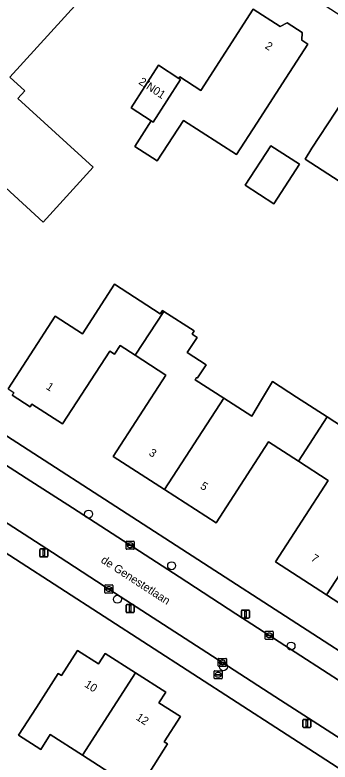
# Model space of a CAD drawing. Extents: x 161139 to 161601, y 381708 to 382245.
# Drawn here: x 161355.3 to 161394.2, y 382017.4 to 382109.7 of the extents above; entities that cross this region are included whole.
import ezdxf

# ---------------------------------------------------------------- set-up
doc = ezdxf.new("R2010")
doc.units = 0
for name, color, linetype in [('IMGEO_Boom', 7, 'Continuous'), ('IMGEO_Brandkraan', 7, 'Continuous'), ('IMGEO_Erf', 7, 'Continuous'), ('IMGEO_Kolk', 7, 'Continuous'), ('IMGEO_Lichtmast', 7, 'Continuous'), ('IMGEO_Openbare_ruimte_label', 7, 'Continuous'), ('IMGEO_Pand', 7, 'Continuous'), ('IMGEO_Pand_nummerreeks', 7, 'Continuous'), ('IMGEO_Rijbaan_lokaal_open', 7, 'Continuous'), ('IMGEO_Voetpad_open', 7, 'Continuous')]:
    doc.layers.add(name, color=color, linetype=linetype)

msp = doc.modelspace()

# ---------------------------------------------------------------- linework, layer by layer
at = {"layer": 'IMGEO_Boom'}
for centre in [(161364.4, 382048.05), (161374.648, 382041.67), (161367.953, 382037.533), (161389.384, 382031.752), (161381.04, 382029.2)]:
    msp.add_circle(centre, 0.489, dxfattribs=at)
at = {"layer": 'IMGEO_Brandkraan'}
for p, q in [((161379.895, 382027.782), (161379.895, 382028.634)), ((161379.97, 382028.708), (161380.822, 382028.708)), ((161380.383, 382028.488), (161380.408, 382028.488)), ((161380.896, 382028.634), (161380.896, 382027.782)), ((161380.822, 382027.708), (161379.97, 382027.708)), ((161380.154, 382028.202), (161380.154, 382028.214)), ((161380.592, 382028.165), (161380.194, 382028.165)), ((161380.197, 382028.251), (161380.595, 382028.251)), ((161380.406, 382027.928), (161380.381, 382027.928)), ((161380.638, 382028.214), (161380.638, 382028.202))]:
    msp.add_line(p, q, dxfattribs=at)
for points in [[(161379.895, 382027.782), (161379.895, 382028.634)], [(161379.97, 382028.708), (161380.822, 382028.708)], [(161380.896, 382028.634), (161380.896, 382027.782)], [(161380.822, 382027.708), (161379.97, 382027.708)]]:
    msp.add_lwpolyline(points, dxfattribs=at)
for centre, radius, start, end in [((161379.972, 382028.632), 0.0765, 91.55205, 178.44795), ((161379.972, 382028.632), 0.0765, 91.55205, 178.44795), ((161380.82, 382028.632), 0.0765, 1.55205, 88.44795), ((161380.82, 382028.632), 0.0765, 1.55205, 88.44795), ((161379.972, 382027.784), 0.0765, 181.55205, 268.44795), ((161379.972, 382027.784), 0.0765, 181.55205, 268.44795), ((161380.194, 382028.211), 0.0403, 85.87752, 175.75265), ((161380.191, 382028.201), 0.0366, 178.93798, 274.71019), ((161380.595, 382028.208), 0.043, 264.86636, 352.45326), ((161380.599, 382028.213), 0.0386, 1.73085, 96.63898), ((161380.82, 382027.784), 0.0765, 271.55205, 358.44795), ((161380.82, 382027.784), 0.0765, 271.55205, 358.44795)]:
    msp.add_arc(centre, radius, start, end, dxfattribs=at)
for centre, major_axis, ratio, start_param, end_param in [((161380.382, 382028.208), (-0.387, 0.002), 0.722429, 4.712389, 7.853982), ((161380.407, 382028.208), (-0.39, 0.002), 0.717154, 1.570796, 4.712389)]:
    msp.add_ellipse(centre, major_axis=major_axis, ratio=ratio, start_param=start_param, end_param=end_param, dxfattribs=at)
at = {"layer": 'IMGEO_Erf'}
for points in [[(161320.525, 382089.631), (161313.623, 382083.997), (161443.483, 382000), (161462.38, 381987.777), (161470.3, 382000), (161498.24, 382043.117), (161359.011, 382133.266)], [(161346.685, 382109.457), (161347.252, 382108.941), (161354.956, 382117.404), (161355.81, 382116.625), (161358.18, 382119.228), (161364.817, 382113.186), (161354.661, 382102.03), (161356.521, 382100.336), (161355.647, 382099.376), (161364.97, 382090.887), (161358.81, 382084.121)], [(161358.81, 382084.121), (161349.515, 382092.582), (161348.62, 382091.598), (161346.729, 382093.319), (161336.5, 382082.084), (161329.934, 382088.061), (161332.405, 382090.775), (161331.456, 382091.639), (161339.157, 382100.098), (161338.619, 382100.588)], [(161354.467, 382063.546), (161357.185, 382067.744), (161360.263, 382072.498), (161363.625, 382070.32), (161367.586, 382076.436), (161373.234, 382072.779), (161373.506, 382073.199), (161373.678, 382073.088), (161377.409, 382070.671), (161377.162, 382070.29), (161377.8, 382069.877), (161376.584, 382067.999), (161378.89, 382066.506), (161377.828, 382064.866), (161377.683, 382064.874), (161377.54, 382064.653), (161381.083, 382062.359), (161384.528, 382060.129), (161385.742, 382062.161), (161387.092, 382064.421), (161390.075, 382062.489), (161393.835, 382060.054), (161397.496, 382057.684)], [(161421.048, 382000), (161306.066, 382074.349)], [(161400.087, 382033.974), (161393.772, 382038.063), (161387.46, 382042.15), (161393.97, 382052.203), (161390.289, 382054.594), (161386.608, 382056.985), (161380.125, 382046.974), (161373.783, 382051.081), (161367.441, 382055.187), (161373.936, 382065.217), (161370.156, 382067.673), (161368.301, 382068.878), (161367.614, 382067.814), (161367.026, 382068.194), (161361.193, 382059.186), (161357.399, 382061.642), (161357.171, 382061.289), (161354.949, 382062.728)]]:
    msp.add_lwpolyline(points, dxfattribs=at)
for points in [[(161376.11, 382096.68), (161372.874, 382091.675), (161370.095, 382093.472), (161372.141, 382096.619), (161369.633, 382098.24), (161373.035, 382103.503), (161375.556, 382101.873), (161375.671, 382102.05), (161378.237, 382100.391), (161384.729, 382110.433), (161388.052, 382108.285), (161388.906, 382108.722), (161390.752, 382107.529), (161390.705, 382106.586), (161391.463, 382106.096), (161388.749, 382101.898), (161385.152, 382096.335), (161382.643, 382092.455)], [(161403.739, 382083.736), (161397.438, 382087.809), (161391.146, 382091.877), (161391.97, 382093.238), (161394.864, 382097.714), (161397.578, 382101.913), (161400.051, 382100.314), (161400.18, 382100.512), (161401.027, 382099.965), (161401.953, 382100.163), (161403.047, 382099.456), (161403.251, 382098.506), (161404.008, 382098.017), (161404.764, 382097.529), (161405.713, 382097.732), (161406.876, 382096.98), (161407.084, 382096.013), (161407.959, 382095.447), (161407.856, 382095.287), (161410.219, 382093.759), (161407.505, 382089.561)], [(161387.254, 382086.383), (161383.725, 382088.664), (161386.887, 382093.556), (161390.416, 382091.275)], [(161359.669, 382020.808), (161358.499, 382018.98), (161355.762, 382020.732), (161357.956, 382024.159), (161360.651, 382028.37), (161361.044, 382028.118), (161363.016, 382031.198), (161365.6, 382029.544), (161366.437, 382030.853), (161370.18, 382028.457), (161373.925, 382026.06), (161373.085, 382024.748), (161375.732, 382023.053), (161373.728, 382019.922), (161374.141, 382019.658), (161371.446, 382015.447), (161369.264, 382012.038), (161366.393, 382013.876), (161367.587, 382015.74), (161363.651, 382018.259)]]:
    msp.add_lwpolyline(points, close=True, dxfattribs=at)
at = {"layer": 'IMGEO_Kolk'}
for p, q in [((161369.03, 382043.778), (161369.03, 382044.63)), ((161369.105, 382044.704), (161369.957, 382044.704)), ((161369.289, 382044.198), (161369.289, 382044.21)), ((161369.727, 382044.161), (161369.329, 382044.161)), ((161369.332, 382044.247), (161369.73, 382044.247)), ((161369.518, 382044.484), (161369.543, 382044.484)), ((161369.773, 382044.21), (161369.773, 382044.198)), ((161370.031, 382044.63), (161370.031, 382043.778)), ((161369.957, 382043.704), (161369.105, 382043.704)), ((161369.541, 382043.924), (161369.516, 382043.924)), ((161366.399, 382038.377), (161366.399, 382039.229)), ((161366.474, 382039.303), (161367.326, 382039.303)), ((161366.658, 382038.797), (161366.658, 382038.809)), ((161367.096, 382038.76), (161366.698, 382038.76)), ((161366.701, 382038.846), (161367.099, 382038.846)), ((161366.91, 382038.523), (161366.885, 382038.523)), ((161366.887, 382039.083), (161366.912, 382039.083)), ((161367.142, 382038.809), (161367.142, 382038.797)), ((161367.4, 382039.229), (161367.4, 382038.377)), ((161367.326, 382038.303), (161366.474, 382038.303)), ((161386.19, 382032.649), (161386.19, 382033.501)), ((161386.265, 382033.575), (161387.117, 382033.575)), ((161386.449, 382033.069), (161386.449, 382033.081)), ((161386.887, 382033.032), (161386.489, 382033.032)), ((161386.492, 382033.118), (161386.89, 382033.118)), ((161386.678, 382033.355), (161386.703, 382033.355)), ((161386.933, 382033.081), (161386.933, 382033.069)), ((161387.191, 382033.501), (161387.191, 382032.649)), ((161387.117, 382032.575), (161386.265, 382032.575)), ((161386.701, 382032.795), (161386.676, 382032.795)), ((161380.41, 382029.306), (161380.41, 382030.158)), ((161380.485, 382030.232), (161381.337, 382030.232)), ((161381.411, 382030.158), (161381.411, 382029.306)), ((161381.337, 382029.232), (161380.485, 382029.232)), ((161380.669, 382029.726), (161380.669, 382029.738)), ((161381.107, 382029.689), (161380.709, 382029.689)), ((161380.712, 382029.775), (161381.11, 382029.775)), ((161380.921, 382029.452), (161380.896, 382029.452)), ((161380.898, 382030.012), (161380.923, 382030.012)), ((161381.153, 382029.738), (161381.153, 382029.726))]:
    msp.add_line(p, q, dxfattribs=at)
for points in [[(161369.03, 382043.778), (161369.03, 382044.63)], [(161369.105, 382044.704), (161369.957, 382044.704)], [(161370.031, 382044.63), (161370.031, 382043.778)], [(161369.957, 382043.704), (161369.105, 382043.704)], [(161366.399, 382038.377), (161366.399, 382039.229)], [(161366.474, 382039.303), (161367.326, 382039.303)], [(161367.4, 382039.229), (161367.4, 382038.377)], [(161367.326, 382038.303), (161366.474, 382038.303)], [(161386.19, 382032.649), (161386.19, 382033.501)], [(161386.265, 382033.575), (161387.117, 382033.575)], [(161387.191, 382033.501), (161387.191, 382032.649)], [(161387.117, 382032.575), (161386.265, 382032.575)], [(161380.41, 382029.306), (161380.41, 382030.158)], [(161380.485, 382030.232), (161381.337, 382030.232)], [(161381.411, 382030.158), (161381.411, 382029.306)], [(161381.337, 382029.232), (161380.485, 382029.232)]]:
    msp.add_lwpolyline(points, dxfattribs=at)
for centre, radius, start, end in [((161369.107, 382044.628), 0.0765, 91.55205, 178.44795), ((161369.107, 382044.628), 0.0765, 91.55205, 178.44795), ((161369.329, 382044.207), 0.0403, 85.87752, 175.75265), ((161369.326, 382044.197), 0.0366, 178.93798, 274.71019), ((161369.73, 382044.204), 0.043, 264.86636, 352.45326), ((161369.734, 382044.209), 0.0386, 1.73085, 96.63898), ((161369.955, 382044.628), 0.0765, 1.55205, 88.44795), ((161369.955, 382044.628), 0.0765, 1.55205, 88.44795), ((161369.107, 382043.78), 0.0765, 181.55205, 268.44795), ((161369.107, 382043.78), 0.0765, 181.55205, 268.44795), ((161369.955, 382043.78), 0.0765, 271.55205, 358.44795), ((161369.955, 382043.78), 0.0765, 271.55205, 358.44795), ((161366.476, 382039.227), 0.0765, 91.55205, 178.44795), ((161366.476, 382039.227), 0.0765, 91.55205, 178.44795), ((161366.698, 382038.806), 0.0403, 85.87752, 175.75265), ((161366.695, 382038.796), 0.0366, 178.93798, 274.71019), ((161367.099, 382038.803), 0.043, 264.86636, 352.45326), ((161367.103, 382038.808), 0.0386, 1.73085, 96.63898), ((161367.324, 382039.227), 0.0765, 1.55205, 88.44795), ((161367.324, 382039.227), 0.0765, 1.55205, 88.44795), ((161366.476, 382038.379), 0.0765, 181.55205, 268.44795), ((161366.476, 382038.379), 0.0765, 181.55205, 268.44795), ((161367.324, 382038.379), 0.0765, 271.55205, 358.44795), ((161367.324, 382038.379), 0.0765, 271.55205, 358.44795), ((161386.267, 382033.499), 0.0765, 91.55205, 178.44795), ((161386.267, 382033.499), 0.0765, 91.55205, 178.44795), ((161386.489, 382033.078), 0.0403, 85.87752, 175.75265), ((161386.486, 382033.068), 0.0366, 178.93798, 274.71019), ((161386.89, 382033.075), 0.043, 264.86636, 352.45326), ((161386.894, 382033.08), 0.0386, 1.73085, 96.63898), ((161387.115, 382033.499), 0.0765, 1.55205, 88.44795), ((161387.115, 382033.499), 0.0765, 1.55205, 88.44795), ((161386.267, 382032.651), 0.0765, 181.55205, 268.44795), ((161386.267, 382032.651), 0.0765, 181.55205, 268.44795), ((161387.115, 382032.651), 0.0765, 271.55205, 358.44795), ((161387.115, 382032.651), 0.0765, 271.55205, 358.44795), ((161380.487, 382030.156), 0.0765, 91.55205, 178.44795), ((161380.487, 382030.156), 0.0765, 91.55205, 178.44795), ((161381.335, 382030.156), 0.0765, 1.55205, 88.44795), ((161381.335, 382030.156), 0.0765, 1.55205, 88.44795), ((161380.487, 382029.308), 0.0765, 181.55205, 268.44795), ((161380.487, 382029.308), 0.0765, 181.55205, 268.44795), ((161380.709, 382029.735), 0.0403, 85.87752, 175.75265), ((161380.706, 382029.725), 0.0366, 178.93798, 274.71019), ((161381.11, 382029.732), 0.043, 264.86636, 352.45326), ((161381.114, 382029.737), 0.0386, 1.73085, 96.63898), ((161381.335, 382029.308), 0.0765, 271.55205, 358.44795), ((161381.335, 382029.308), 0.0765, 271.55205, 358.44795)]:
    msp.add_arc(centre, radius, start, end, dxfattribs=at)
for centre, major_axis, ratio, start_param, end_param in [((161369.517, 382044.204), (-0.387, 0.002), 0.722429, 4.712389, 7.853982), ((161369.542, 382044.204), (-0.39, 0.002), 0.717154, 1.570796, 4.712389), ((161366.886, 382038.803), (-0.387, 0.002), 0.722429, 4.712389, 7.853982), ((161366.911, 382038.803), (-0.39, 0.002), 0.717154, 1.570796, 4.712389), ((161386.677, 382033.075), (-0.387, 0.002), 0.722429, 4.712389, 7.853982), ((161386.702, 382033.075), (-0.39, 0.002), 0.717154, 1.570796, 4.712389), ((161380.897, 382029.732), (-0.387, 0.002), 0.722429, 4.712389, 7.853982), ((161380.922, 382029.732), (-0.39, 0.002), 0.717154, 1.570796, 4.712389)]:
    msp.add_ellipse(centre, major_axis=major_axis, ratio=ratio, start_param=start_param, end_param=end_param, dxfattribs=at)
at = {"layer": 'IMGEO_Lichtmast'}
for p, q in [((161358.366, 382042.857), (161358.366, 382043.657)), ((161358.366, 382043.657), (161358.366, 382042.857)), ((161358.466, 382043.757), (161359.256, 382043.757)), ((161359.256, 382043.757), (161358.466, 382043.757)), ((161359.356, 382043.657), (161359.356, 382042.857)), ((161359.356, 382042.857), (161359.356, 382043.657)), ((161359.256, 382042.757), (161358.466, 382042.757)), ((161358.466, 382042.757), (161359.256, 382042.757)), ((161369.024, 382035.985), (161369.024, 382036.785)), ((161369.024, 382036.785), (161369.024, 382035.985)), ((161369.124, 382036.885), (161369.914, 382036.885)), ((161369.914, 382036.885), (161369.124, 382036.885)), ((161370.014, 382036.785), (161370.014, 382035.985)), ((161370.014, 382035.985), (161370.014, 382036.785)), ((161369.914, 382035.885), (161369.124, 382035.885)), ((161369.124, 382035.885), (161369.914, 382035.885)), ((161383.26, 382035.3), (161383.26, 382036.1)), ((161383.26, 382036.1), (161383.26, 382035.3)), ((161383.36, 382036.2), (161384.15, 382036.2)), ((161384.15, 382036.2), (161383.36, 382036.2)), ((161384.25, 382036.1), (161384.25, 382035.3)), ((161384.25, 382035.3), (161384.25, 382036.1)), ((161384.15, 382035.2), (161383.36, 382035.2)), ((161383.36, 382035.2), (161384.15, 382035.2)), ((161390.836, 382021.791), (161390.836, 382022.591)), ((161390.836, 382022.591), (161390.836, 382021.791)), ((161390.936, 382022.691), (161391.726, 382022.691)), ((161391.726, 382022.691), (161390.936, 382022.691)), ((161391.826, 382022.591), (161391.826, 382021.791)), ((161391.826, 382021.791), (161391.826, 382022.591)), ((161391.726, 382021.691), (161390.936, 382021.691)), ((161390.936, 382021.691), (161391.726, 382021.691))]:
    msp.add_line(p, q, dxfattribs=at)
for points in [[(161358.786, 382043.632), (161358.936, 382043.632), (161358.936, 382042.882), (161358.786, 382042.882), (161358.786, 382043.632)], [(161369.444, 382036.76), (161369.594, 382036.76), (161369.594, 382036.01), (161369.444, 382036.01), (161369.444, 382036.76)], [(161383.68, 382036.075), (161383.83, 382036.075), (161383.83, 382035.325), (161383.68, 382035.325), (161383.68, 382036.075)], [(161391.256, 382022.566), (161391.406, 382022.566), (161391.406, 382021.816), (161391.256, 382021.816), (161391.256, 382022.566)]]:
    msp.add_lwpolyline(points, dxfattribs=at)
for centre, start, end in [((161358.466, 382043.657), 90, 180), ((161358.466, 382043.657), 90, 180), ((161359.256, 382043.657), 0, 90), ((161359.256, 382043.657), 360, 90), ((161358.466, 382042.857), 180, 270), ((161358.466, 382042.857), 180, 270), ((161359.256, 382042.857), 270, 0), ((161359.256, 382042.857), 270, 0), ((161369.124, 382036.785), 90, 180), ((161369.124, 382036.785), 90, 180), ((161369.914, 382036.785), 0, 90), ((161369.914, 382036.785), 360, 90), ((161369.124, 382035.985), 180, 270), ((161369.124, 382035.985), 180, 270), ((161369.914, 382035.985), 270, 0), ((161369.914, 382035.985), 270, 0), ((161383.36, 382036.1), 90, 180), ((161383.36, 382036.1), 90, 180), ((161384.15, 382036.1), 0, 90), ((161384.15, 382036.1), 360, 90), ((161383.36, 382035.3), 180, 270), ((161383.36, 382035.3), 180, 270), ((161384.15, 382035.3), 270, 0), ((161384.15, 382035.3), 270, 0), ((161390.936, 382022.591), 90, 180), ((161390.936, 382022.591), 90, 180), ((161391.726, 382022.591), 0, 90), ((161391.726, 382022.591), 360, 90), ((161390.936, 382021.791), 180, 270), ((161390.936, 382021.791), 180, 270), ((161391.726, 382021.791), 270, 0), ((161391.726, 382021.791), 270, 0)]:
    msp.add_arc(centre, 0.1, start, end, dxfattribs=at)
at = {"layer": 'IMGEO_Pand'}
msp.add_lwpolyline([(161338.619, 382100.588), (161339.157, 382100.098), (161331.456, 382091.639), (161332.405, 382090.775), (161329.934, 382088.061), (161336.5, 382082.084), (161346.729, 382093.319), (161348.62, 382091.598), (161349.515, 382092.582), (161358.81, 382084.121), (161364.97, 382090.887), (161355.647, 382099.376), (161356.521, 382100.336), (161354.661, 382102.03), (161364.817, 382113.186), (161358.18, 382119.228), (161355.81, 382116.625), (161354.956, 382117.404), (161347.252, 382108.941), (161346.685, 382109.457)], dxfattribs=at)
for points in [[(161388.749, 382101.898), (161391.463, 382106.096), (161390.705, 382106.586), (161390.752, 382107.529), (161388.906, 382108.722), (161388.052, 382108.285), (161384.729, 382110.433), (161378.237, 382100.391), (161375.671, 382102.05), (161375.556, 382101.873), (161375.755, 382101.744), (161372.353, 382096.482), (161372.141, 382096.619), (161370.095, 382093.472), (161372.874, 382091.675), (161376.11, 382096.68), (161382.643, 382092.455), (161385.152, 382096.335)], [(161375.556, 382101.873), (161373.035, 382103.503), (161369.633, 382098.24), (161372.141, 382096.619), (161372.353, 382096.482), (161375.755, 382101.744)], [(161397.438, 382087.809), (161404.008, 382098.017), (161403.251, 382098.506), (161403.047, 382099.456), (161401.953, 382100.163), (161401.027, 382099.965), (161400.18, 382100.512), (161400.051, 382100.314), (161397.578, 382101.913), (161394.864, 382097.714), (161391.97, 382093.238), (161391.146, 382091.877)], [(161387.254, 382086.383), (161390.416, 382091.275), (161386.887, 382093.556), (161383.725, 382088.664)], [(161373.678, 382073.088), (161373.506, 382073.199), (161373.234, 382072.779), (161367.586, 382076.436), (161363.625, 382070.32), (161360.263, 382072.498), (161357.185, 382067.744), (161354.467, 382063.546), (161355.18, 382063.085), (161354.949, 382062.728), (161357.171, 382061.289), (161357.399, 382061.642), (161361.193, 382059.186), (161367.026, 382068.194), (161367.614, 382067.814), (161368.301, 382068.878), (161370.156, 382067.673)], [(161373.678, 382073.088), (161370.156, 382067.673), (161373.936, 382065.217), (161367.441, 382055.187), (161373.783, 382051.081), (161381.083, 382062.359), (161377.54, 382064.653), (161377.683, 382064.874), (161377.828, 382064.866), (161378.89, 382066.506), (161376.584, 382067.999), (161377.8, 382069.877), (161377.162, 382070.29), (161377.409, 382070.671)], [(161386.608, 382056.985), (161390.289, 382054.594), (161393.835, 382060.054), (161390.075, 382062.489), (161387.092, 382064.421), (161385.742, 382062.161), (161384.528, 382060.129), (161381.083, 382062.359), (161373.783, 382051.081), (161380.125, 382046.974)], [(161393.772, 382038.063), (161401.11, 382049.396), (161397.803, 382051.538), (161399.046, 382053.458), (161396.573, 382055.059), (161397.487, 382056.47), (161396.939, 382056.824), (161397.496, 382057.684), (161393.835, 382060.054), (161390.289, 382054.594), (161393.97, 382052.203), (161387.46, 382042.15)], [(161401.11, 382049.396), (161393.772, 382038.063), (161400.087, 382033.974), (161406.584, 382044.008), (161410.358, 382041.557), (161413.97, 382047.113), (161410.222, 382049.541), (161408.654, 382047.119), (161405.696, 382049.035), (161404.506, 382047.197)], [(161370.18, 382028.457), (161366.437, 382030.853), (161365.6, 382029.544), (161363.016, 382031.198), (161361.044, 382028.118), (161360.651, 382028.37), (161357.956, 382024.159), (161355.762, 382020.732), (161358.499, 382018.98), (161359.669, 382020.808), (161363.651, 382018.259)], [(161370.18, 382028.457), (161363.651, 382018.259), (161367.587, 382015.74), (161366.393, 382013.876), (161369.264, 382012.038), (161371.446, 382015.447), (161374.141, 382019.658), (161373.728, 382019.922), (161375.732, 382023.053), (161373.085, 382024.748), (161373.925, 382026.06)]]:
    msp.add_lwpolyline(points, close=True, dxfattribs=at)
at = {"layer": 'IMGEO_Rijbaan_lokaal_open'}
for points in [[(161375.585, 382040.285), (161362.411, 382048.813), (161356.674, 382052.498), (161311.536, 382081.664), (161306.338, 382077.878), (161325.321, 382065.668), (161328.504, 382063.628), (161339.032, 382056.795), (161345.442, 382052.667), (161359.944, 382043.32), (161366.307, 382039.161), (161381.679, 382029.228), (161388.068, 382025.069), (161398.439, 382018.395)], [(161470.897, 381978.482), (161460.91, 381984.988), (161458.647, 381986.439), (161425.551, 382007.922), (161421.741, 382010.379), (161420.042, 382011.494), (161416.852, 382013.552), (161402.927, 382022.535), (161395.928, 382027.083), (161382.572, 382035.748), (161375.585, 382040.285)]]:
    msp.add_lwpolyline(points, dxfattribs=at)
at = {"layer": 'IMGEO_Voetpad_open'}
for points in [[(161313.623, 382083.997), (161311.536, 382081.664), (161356.674, 382052.498), (161362.411, 382048.813), (161375.585, 382040.285), (161382.572, 382035.748), (161395.928, 382027.083), (161402.927, 382022.535), (161416.852, 382013.552), (161420.042, 382011.494), (161421.741, 382010.379), (161425.551, 382007.922), (161458.647, 381986.439), (161460.91, 381984.988)], [(161464.955, 381985.959), (161462.38, 381987.777), (161443.483, 382000), (161313.623, 382083.997)], [(161398.439, 382018.395), (161388.068, 382025.069), (161381.679, 382029.228), (161366.307, 382039.161), (161359.944, 382043.32), (161345.442, 382052.667), (161339.032, 382056.795), (161328.504, 382063.628), (161325.321, 382065.668), (161306.338, 382077.878), (161302.036, 382073.583), (161301.893, 382073.339)], [(161306.066, 382074.349), (161421.048, 382000), (161474.804, 381965.241), (161478.068, 381963.057), (161478.909, 381962.515)]]:
    msp.add_lwpolyline(points, dxfattribs=at)

# ---------------------------------------------------------------- texts
at = {"layer": 'IMGEO_Openbare_ruimte_label'}
msp.add_text('de Genestetlaan', height=1, rotation=327.04099, dxfattribs=at).set_placement((161365.832, 382042.144))
at = {"layer": 'IMGEO_Pand_nummerreeks'}
for s, rotation, p in [('2', 327.21535, (161386.087, 382105.656)), ('2/N01', 326.67105, (161370.489, 382101.247)), ('1', 327.04745, (161359.065, 382063.568)), ('3', 327.07659, (161371.75, 382055.399)), ('5', 327.07785, (161378.092, 382051.292)), ('7', 327.07689, (161391.755, 382042.371)), ('10', 327.35915, (161363.809, 382026.795)), ('12', 327.35915, (161370.162, 382022.725))]:
    msp.add_text(s, height=1, rotation=rotation, dxfattribs=at).set_placement(p)

doc.saveas('drawing.dxf')
